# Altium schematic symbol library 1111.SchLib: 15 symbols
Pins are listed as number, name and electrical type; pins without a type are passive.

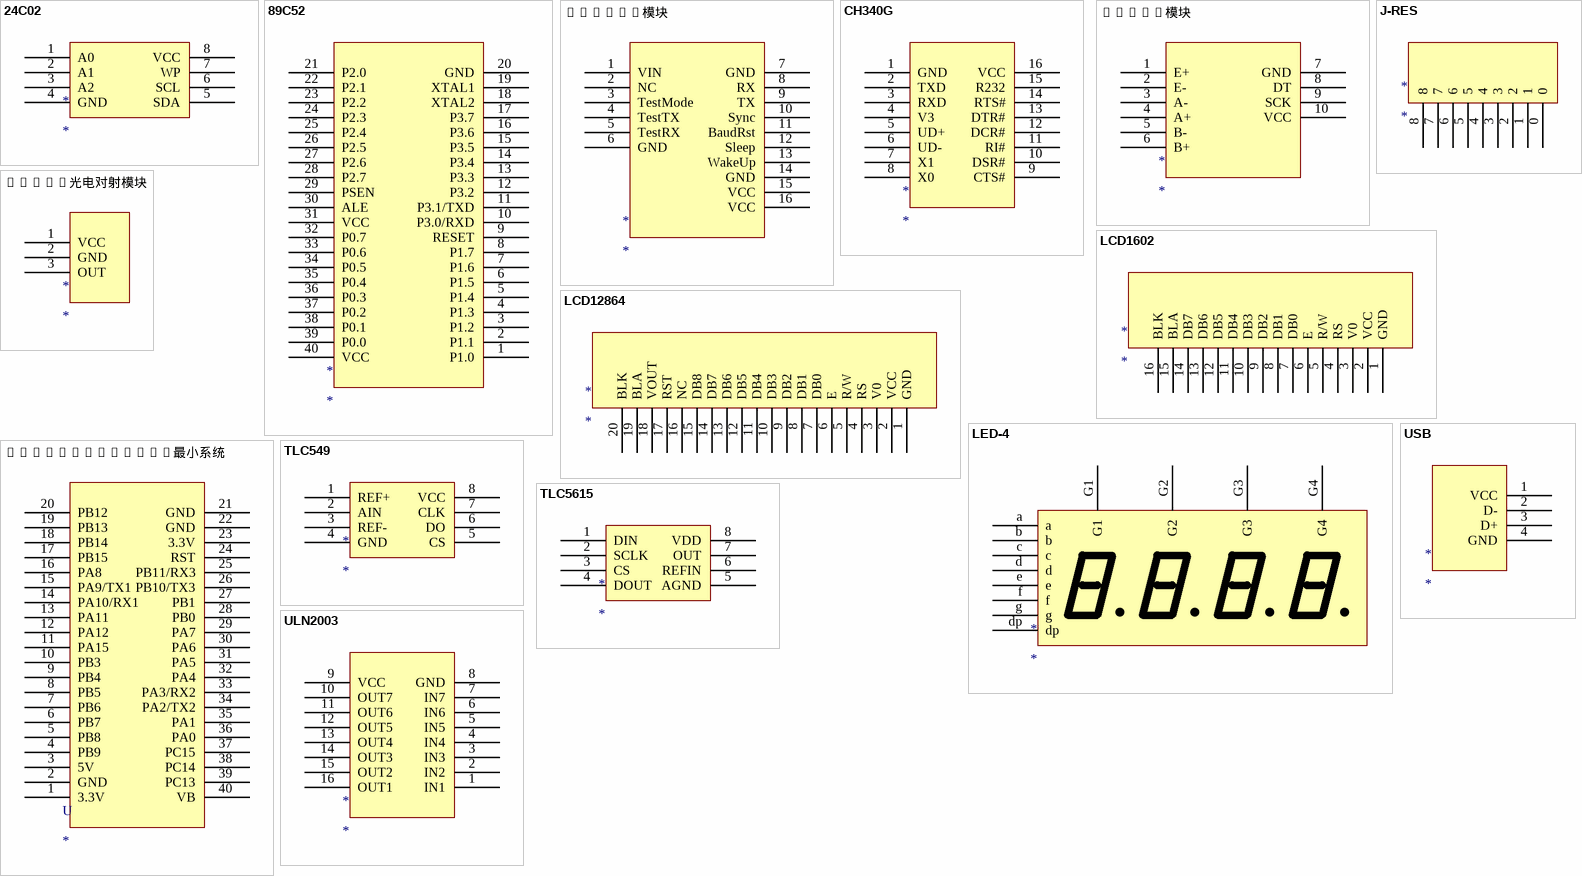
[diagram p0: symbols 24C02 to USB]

## 24C02
designator *
pins: 1 A0, 2 A1, 3 A2, 4 GND, 5 SDA, 6 SCL, 7 WP, 8 VCC

## 89C52
designator *
pins: 1 P1.0, 2 P1.1, 3 P1.2, 4 P1.3, 5 P1.4, 6 P1.5, 7 P1.6, 8 P1.7, 9 RESET, 10 P3.0/RXD, 11 P3.1/TXD, 12 P3.2, 13 P3.3, 14 P3.4, 15 P3.5, 16 P3.6, 17 P3.7, 18 XTAL2, 19 XTAL1, 20 GND, 21 P2.0, 22 P2.1, 23 P2.2, 24 P2.3, 25 P2.4, 26 P2.5, 27 P2.6, 28 P2.7, 29 PSEN, 30 ALE, 31 VCC, 32 P0.7, 33 P0.6, 34 P0.5, 35 P0.4, 36 P0.3, 37 P0.2, 38 P0.1, 39 P0.0, 40 VCC

## CC2530模块
designator *
pins: 1 VIN, 2 NC, 3 TestMode, 4 TestTX, 5 TestRX, 6 GND, 7 GND, 8 RX, 9 TX, 10 Sync, 11 BaudRst, 12 Sleep, 13 WakeUp, 14 GND, 15 VCC, 16 VCC

## CH340G
designator *
pins: 1 GND, 2 TXD, 3 RXD, 4 V3, 5 UD+, 6 UD-, 7 X1, 8 X0, 9 CTS#, 10 DSR#, 11 RI#, 12 DCR#, 13 DTR#, 14 RTS#, 15 R232, 16 VCC

## HX711模块
designator *
pins: 1 E+, 2 E-, 3 A-, 4 A+, 5 B-, 6 B+, 7 GND, 8 DT, 9 SCK, 10 VCC

## J-RES
designator *
pins: 0, 1, 2, 3, 4, 5, 6, 7, 8

## LCD1602
designator *
pins: 1 GND, 2 VCC, 3 V0, 4 RS, 5 R/W, 6 E, 7 DB0, 8 DB1, 9 DB2, 10 DB3, 11 DB4, 12 DB5, 13 DB6, 14 DB7, 15 BLA, 16 BLK

## LCD12864
designator *
pins: 1 GND, 2 VCC, 3 V0, 4 RS, 5 R/W, 6 E, 7 DB0, 8 DB1, 9 DB2, 10 DB3, 11 DB4, 12 DB5, 13 DB6, 14 DB7, 15 DB8, 16 NC, 17 RST, 18 VOUT, 19 BLA, 20 BLK

## LED-4
designator *
pins: a, b, c, d, dp, e, f, g, G1, G2, G3, G4

## LM393光电对射模块
designator *
pins: 1 VCC, 2 GND, 3 OUT

## stm32f103c8t6最小系统
designator U
pins: 1 3.3V, 2 GND, 3 5V, 4 PB9, 5 PB8, 6 PB7, 7 PB6, 8 PB5, 9 PB4, 10 PB3, 11 PA15, 12 PA12, 13 PA11, 14 PA10/RX1, 15 PA9/TX1, 16 PA8, 17 PB15, 18 PB14, 19 PB13, 20 PB12, 21 GND, 22 GND, 23 3.3V, 24 RST, 25 PB11/RX3, 26 PB10/TX3, 27 PB1, 28 PB0, 29 PA7, 30 PA6, 31 PA5, 32 PA4, 33 PA3/RX2, 34 PA2/TX2, 35 PA1, 36 PA0, 37 PC15, 38 PC14, 39 PC13, 40 VB

## TLC549
designator *
pins: 1 REF+, 2 AIN, 3 REF-, 4 GND, 5 CS, 6 DO, 7 CLK, 8 VCC

## TLC5615
designator *
pins: 1 DIN, 2 SCLK, 3 CS, 4 DOUT, 5 AGND, 6 REFIN, 7 OUT, 8 VDD

## ULN2003
designator *
pins: 1 IN1, 2 IN2, 3 IN3, 4 IN4, 5 IN5, 6 IN6, 7 IN7, 8 GND, 9 VCC, 10 OUT7, 11 OUT6, 12 OUT5, 13 OUT4, 14 OUT3, 15 OUT2, 16 OUT1

## USB
designator *
pins: 1 VCC, 2 D-, 3 D+, 4 GND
